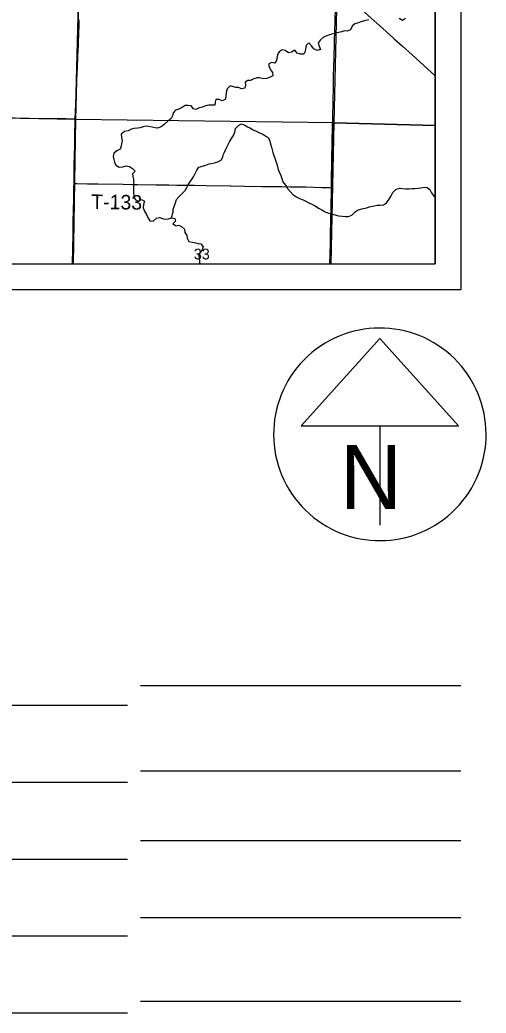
# Model space of a CAD drawing. Extents: x 0 to 45.9, y 0 to 22.
# Drawn here: x 7.28 to 9.099, y 11.177 to 15.053 of the extents above; entities that cross this region are included whole.
import ezdxf

# ---------------------------------------------------------------- set-up
doc = ezdxf.new("R2010")
doc.units = 0
for name, color, linetype in [('Default', 7, 'Continuous'), ('GM_X_County_Road', 7, 'Continuous'), ('GM_X_Minor_River', 7, 'Continuous'), ('GM_X_Section', 7, 'Continuous'), ('GM_X_Section_Text', 7, 'Continuous'), ('GM_X_State_Route', 7, 'Continuous'), ('GM_X_Township_Road', 7, 'Continuous'), ('GM_X_Township_Road_Text', 7, 'Continuous'), ('SH_Cut_Line', 7, 'Continuous'), ('SH_Text', 7, 'Continuous')]:
    doc.layers.add(name, color=color, linetype=linetype)

msp = doc.modelspace()

# ---------------------------------------------------------------- linework, layer by layer
at = {"layer": 'Default'}
msp.add_lwpolyline([(5.4606, 15.6588), (5.4538, 14.1), (8.9, 14.1), (8.9, 19.7611)], dxfattribs=at)
for points in [[(8.9, 14.6398), (8.9, 15.6495), (8.5286, 15.6561), (8.5052, 14.6503)], [(6.4798, 14.1), (7.4874, 14.1), (7.4967, 14.6639), (6.4893, 14.6816)], [(7.4874, 14.1), (8.4929, 14.1), (8.5052, 14.6503), (7.4967, 14.6639)], [(8.4929, 14.1), (8.9, 14.1), (8.9, 14.6398), (8.5052, 14.6503)]]:
    msp.add_lwpolyline(points, close=True, dxfattribs=at)
at = {"layer": 'GM_X_County_Road'}
for points in [[(8.4956, 14.3977), (8.4962, 14.4285), (8.4974, 14.4999), (8.4987, 14.581), (8.4998, 14.6307), (8.5005, 14.6708), (8.502, 14.7364), (8.5034, 14.7858), (8.504, 14.8264), (8.5053, 14.876), (8.5057, 14.8978), (8.5063, 14.9199), (8.5073, 14.9473), (8.5078, 14.9752), (8.5085, 15.0033), (8.5099, 15.0527), (8.5109, 15.0966), (8.5118, 15.1429), (8.5119, 15.1617), (8.5129, 15.1706), (8.514, 15.1742), (8.5158, 15.1766), (8.5183, 15.1797)], [(7.496, 14.6661), (7.4983, 14.7239), (7.5012, 14.7984), (7.5042, 14.8667), (7.5058, 14.9102), (7.5078, 14.9567), (7.5096, 15.0033), (7.5108, 15.0312), (7.5116, 15.0529)], [(6.4922, 14.6848), (6.4995, 14.6846), (6.5306, 14.6838), (6.6454, 14.6815), (6.723, 14.6799), (6.7664, 14.6789), (6.8161, 14.678), (6.9185, 14.6762), (7.0116, 14.6744), (7.0457, 14.6739), (7.1357, 14.6725), (7.2071, 14.6713), (7.3157, 14.6695), (7.3933, 14.6683), (7.4585, 14.6672), (7.4866, 14.6668), (7.496, 14.6661)], [(7.4911, 14.4145), (7.492, 14.4878), (7.4928, 14.522), (7.4936, 14.5624), (7.4944, 14.6028), (7.4959, 14.6618), (7.496, 14.6661)], [(7.4848, 14.1), (7.4849, 14.1027), (7.487, 14.2145), (7.4881, 14.2611), (7.4891, 14.3108), (7.4896, 14.3512), (7.4908, 14.4009), (7.4911, 14.4145)], [(8.4897, 14.1), (8.4904, 14.1364), (8.4914, 14.1799), (8.4921, 14.2172), (8.493, 14.27), (8.494, 14.3166), (8.4956, 14.3977)]]:
    msp.add_lwpolyline(points, dxfattribs=at)
at = {"layer": 'GM_X_Minor_River'}
msp.add_line((7.9801, 14.1037), (7.9867, 14.1), dxfattribs=at)
for points in [[(8.6416, 15.0533), (8.6242, 15.0484), (8.6102, 15.0445), (8.5973, 15.0399), (8.5871, 15.0365), (8.5765, 15.0277), (8.5697, 15.014), (8.5572, 15.0091), (8.5454, 15.0094), (8.5356, 15.006), (8.5231, 15.0033), (8.5102, 15.0002), (8.5007, 14.9986), (8.4886, 14.9944), (8.475, 14.9895), (8.4651, 14.9852), (8.4523, 14.9746), (8.4443, 14.9628), (8.4474, 14.9503), (8.4531, 14.9374), (8.4399, 14.9336), (8.4273, 14.9396), (8.4174, 14.9517), (8.4075, 14.9631), (8.3966, 14.9528), (8.3947, 14.9391), (8.3936, 14.9289), (8.3872, 14.919), (8.3743, 14.919), (8.3622, 14.9231), (8.3526, 14.934), (8.3398, 14.9268), (8.3276, 14.9245), (8.3155, 14.9328), (8.3033, 14.9354), (8.2912, 14.9282), (8.2852, 14.9179), (8.2837, 14.908), (8.2815, 14.8944)], [(8.785, 15.058), (8.7725, 15.0507), (8.7603, 15.0575)], [(8.2815, 14.8944), (8.2751, 14.883), (8.2618, 14.886), (8.25, 14.8798), (8.2523, 14.8704), (8.2577, 14.8579), (8.2657, 14.8473), (8.2669, 14.834), (8.2544, 14.8283), (8.2415, 14.8244), (8.2305, 14.8229), (8.2153, 14.8259), (8.2058, 14.8266), (8.1922, 14.8231), (8.1797, 14.8159), (8.1698, 14.8155), (8.1585, 14.8098), (8.16, 14.7984), (8.1578, 14.7859), (8.1449, 14.7828), (8.1331, 14.7881), (8.1229, 14.7888), (8.1134, 14.7918), (8.1005, 14.7948), (8.0888, 14.7834), (8.085, 14.7693), (8.084, 14.7553), (8.0813, 14.7416), (8.0685, 14.7363), (8.0571, 14.7419), (8.0442, 14.7415), (8.0412, 14.7312), (8.0405, 14.7191), (8.0268, 14.7194), (8.0166, 14.7202), (8.0041, 14.7171), (7.9919, 14.7121), (7.979, 14.709), (7.9662, 14.7025), (7.9567, 14.7055), (7.9487, 14.7173), (7.9358, 14.718), (7.9251, 14.7187), (7.913, 14.7111), (7.8994, 14.7038), (7.8865, 14.7004), (7.8782, 14.6897), (7.8756, 14.678), (7.8699, 14.6681), (7.8567, 14.6574), (7.8442, 14.646), (7.8314, 14.635), (7.817, 14.6296), (7.8071, 14.6307), (7.7953, 14.6341), (7.7821, 14.6371), (7.7726, 14.6378), (7.7601, 14.6351), (7.7495, 14.6313), (7.7388, 14.6305), (7.7259, 14.6282), (7.715, 14.6255), (7.7025, 14.6197), (7.6881, 14.6167), (7.6748, 14.6071), (7.676, 14.5942), (7.6791, 14.5806), (7.6765, 14.5707), (7.6754, 14.5593), (7.6705, 14.5479), (7.658, 14.5411), (7.6463, 14.5323), (7.644, 14.519), (7.646, 14.5077), (7.6483, 14.4978), (7.6544, 14.4857), (7.6677, 14.4781), (7.6813, 14.4797), (7.695, 14.4828), (7.7075, 14.4802), (7.7193, 14.4722), (7.73, 14.462), (7.719, 14.4514), (7.7202, 14.4412), (7.7225, 14.4313), (7.7233, 14.4188), (7.7237, 14.4093), (7.7234, 14.3994), (7.7226, 14.39), (7.7231, 14.3786), (7.7246, 14.3653), (7.7292, 14.3517), (7.7418, 14.3449), (7.7543, 14.351), (7.7657, 14.3457), (7.7623, 14.3321), (7.7601, 14.3192), (7.7658, 14.3063), (7.7738, 14.2927), (7.7784, 14.2809), (7.7868, 14.2688)], [(7.8717, 14.2801), (7.8773, 14.3036), (7.8781, 14.3131), (7.8822, 14.3249), (7.8863, 14.3385), (7.8908, 14.3511), (7.9014, 14.3629), (7.912, 14.3743), (7.9241, 14.3861), (7.9316, 14.3982), (7.9369, 14.4085), (7.9429, 14.4195), (7.9493, 14.429), (7.9569, 14.44), (7.9633, 14.453), (7.9701, 14.4666), (7.978, 14.4784), (7.9924, 14.4819), (8.0049, 14.4853), (8.0178, 14.4907), (8.0272, 14.4926), (8.039, 14.4949), (8.0526, 14.4984), (8.0659, 14.5068), (8.0719, 14.5182), (8.0745, 14.5281), (8.0798, 14.5383), (8.0847, 14.5508), (8.0915, 14.5634), (8.0971, 14.5763), (8.1058, 14.5892), (8.113, 14.6014), (8.1182, 14.6147), (8.1216, 14.6283), (8.1322, 14.6398), (8.145, 14.6466), (8.1576, 14.6414), (8.1675, 14.6357), (8.177, 14.6308), (8.1903, 14.6229), (8.2024, 14.618), (8.215, 14.6116), (8.2252, 14.6074), (8.2381, 14.5999), (8.2499, 14.592), (8.2549, 14.5795), (8.258, 14.5677), (8.2614, 14.5552), (8.2641, 14.5454), (8.2672, 14.5355), (8.271, 14.523), (8.2752, 14.5124), (8.2783, 14.5018), (8.2822, 14.4901), (8.2848, 14.4802), (8.2879, 14.4692), (8.2917, 14.4594), (8.2982, 14.4457), (8.3021, 14.4336), (8.3063, 14.42), (8.3158, 14.4071), (8.3246, 14.395), (8.3341, 14.3833), (8.3459, 14.37), (8.3592, 14.3625), (8.3714, 14.3557), (8.3847, 14.3497), (8.395, 14.3448), (8.4052, 14.3395), (8.4185, 14.3331), (8.4318, 14.3271), (8.4451, 14.3184), (8.458, 14.3116), (8.4717, 14.3029), (8.4843, 14.2984), (8.4945, 14.2951), (8.5086, 14.2913), (8.5234, 14.2879), (8.537, 14.2861), (8.5499, 14.2854), (8.5621, 14.2847), (8.5746, 14.2908), (8.5878, 14.3037), (8.5995, 14.3113), (8.6098, 14.3133), (8.6196, 14.316), (8.6333, 14.3194), (8.6427, 14.3225), (8.6624, 14.3271), (8.6734, 14.3298), (8.6856, 14.3298), (8.6992, 14.3303), (8.711, 14.3386), (8.7208, 14.3523), (8.7291, 14.366), (8.7358, 14.3793), (8.7464, 14.3907), (8.7608, 14.3953), (8.7733, 14.3942), (8.7862, 14.3927), (8.7995, 14.3935)], [(8.7995, 14.3935), (8.809, 14.3951), (8.8215, 14.3951), (8.8344, 14.3959), (8.8439, 14.3971), (8.8587, 14.3991), (8.8689, 14.3987), (8.8792, 14.3912), (8.8857, 14.3775), (8.8948, 14.3647), (8.9, 14.3623)], [(7.7868, 14.2688), (7.7993, 14.2673), (7.8126, 14.2784), (7.8262, 14.2818), (7.8361, 14.2773), (7.8467, 14.2743), (7.8592, 14.2763), (7.8717, 14.2801), (7.8846, 14.2775), (7.8873, 14.2672), (7.876, 14.2573), (7.8893, 14.2483), (7.8988, 14.251), (7.9109, 14.2461), (7.9227, 14.2363), (7.9235, 14.2226), (7.9311, 14.2109), (7.9327, 14.201), (7.9388, 14.1881), (7.9532, 14.1852), (7.9661, 14.1829), (7.976, 14.1803), (7.9859, 14.1784), (7.9954, 14.1671), (7.9905, 14.1553), (7.983, 14.1454), (7.9785, 14.1329), (7.9793, 14.1234), (7.9801, 14.1136), (7.9801, 14.1037), (7.9798, 14.1)]]:
    msp.add_lwpolyline(points, dxfattribs=at)
at = {"layer": 'GM_X_Section'}
for points in [[(7.5224, 15.6742), (7.4967, 14.6639), (6.4893, 14.6816), (6.5014, 15.6897)], [(8.5286, 15.6561), (8.5052, 14.6503), (7.4967, 14.6639), (7.5224, 15.6742)]]:
    msp.add_lwpolyline(points, close=True, dxfattribs=at)
at = {"layer": 'GM_X_State_Route'}
for points in [[(8.3608, 15.325), (8.3893, 15.2983), (8.4304, 15.2603), (8.4829, 15.2119), (8.5059, 15.1909), (8.5183, 15.1797), (8.5515, 15.1496), (8.5795, 15.1241), (8.6395, 15.07), (8.6949, 15.0201), (8.7395, 14.9798)], [(8.7395, 14.9798), (8.741, 14.9784), (8.7734, 14.9494), (8.8102, 14.9159), (8.8563, 14.8743), (8.9, 14.8348)]]:
    msp.add_lwpolyline(points, dxfattribs=at)
at = {"layer": 'GM_X_Township_Road'}
for points in [[(7.4911, 14.4145), (7.4998, 14.4142), (7.5029, 14.4142), (7.5433, 14.4131), (7.5837, 14.4126), (7.6832, 14.4111), (7.7174, 14.4105), (7.7391, 14.4101), (7.8107, 14.4091), (7.8604, 14.4084), (7.8915, 14.4081), (7.9257, 14.4078), (7.9599, 14.4076), (8.0065, 14.4067), (8.1009, 14.4046)], [(8.1009, 14.4046), (8.1029, 14.4045), (8.1557, 14.4036), (8.2241, 14.4028), (8.2615, 14.4023), (8.3019, 14.4017), (8.3361, 14.4013), (8.3951, 14.4005), (8.4573, 14.399), (8.4884, 14.398), (8.4956, 14.3977)]]:
    msp.add_lwpolyline(points, dxfattribs=at)
at = {"layer": 'SH_Cut_Line'}
for p, q in [((9, 21), (9, 14)), ((8.9, 20.9), (8.9, 14.1)), ((2.1, 14.1), (8.9, 14.1)), ((2, 14), (9, 14)), ((8.6845, 13.8091), (8.3769, 13.4678)), ((8.9921, 13.4678), (8.6845, 13.8091)), ((8.3769, 13.4678), (8.9921, 13.4678)), ((8.6845, 13.4678), (8.6845, 13.0811)), ((8.6845, 13.4353), (8.6845, 13.4353)), ((8.6845, 13.4353), (8.6845, 13.4353)), ((7.75, 12.4553), (9, 12.4553)), ((7.7, 12.3767), (4.4937, 12.3767)), ((9, 12.1207), (7.75, 12.1207)), ((7.7, 12.0767), (3.9895, 12.0767)), ((9, 11.8491), (7.75, 11.8491)), ((7.7, 11.7767), (3.6192, 11.7767)), ((9, 11.5491), (7.75, 11.5491)), ((7.7, 11.4767), (3.3288, 11.4767)), ((9, 11.2223), (7.75, 11.2223)), ((7.7, 11.1767), (4.7452, 11.1767))]:
    msp.add_line(p, q, dxfattribs=at)
msp.add_arc((8.6845, 13.4353), 0.4148, 129.7798, 129.7633, dxfattribs=at)
at = {"layer": 'SH_Text'}
msp.add_lwpolyline([(5.4606, 15.6588), (5.4538, 14.1), (8.9, 14.1), (8.9, 19.7611)], dxfattribs=at)

# ---------------------------------------------------------------- texts
at = {"layer": 'GM_X_Section_Text'}
msp.add_text('33', height=0.04186, rotation=0, dxfattribs=at).set_placement((7.9585, 14.1176))
at = {"layer": 'GM_X_Township_Road_Text'}
msp.add_text('T-133', height=0.05682, rotation=359.1612, dxfattribs=at).set_placement((7.5578, 14.3147))
at = {"layer": 'SH_Cut_Line'}
msp.add_text('N', height=0.25, dxfattribs=at).set_placement((8.5292, 13.144))

doc.saveas('drawing.dxf')
